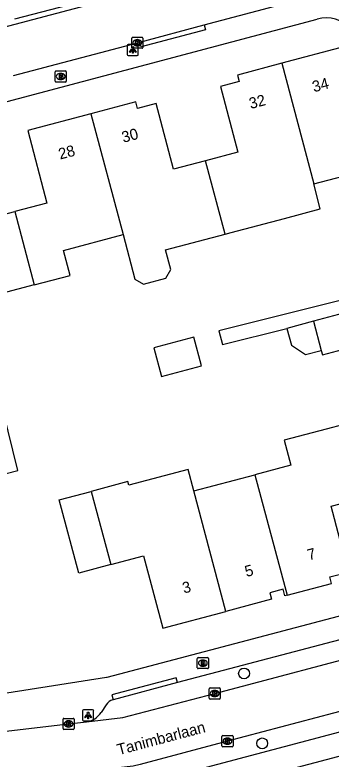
# Model space of a CAD drawing. Extents: x 162880 to 165536, y 384011 to 385179.
# Drawn here: x 163816.8 to 163845.3, y 384374.7 to 384441.9 of the extents above; entities that cross this region are included whole.
import ezdxf

# ---------------------------------------------------------------- set-up
doc = ezdxf.new("R2010")
doc.units = 0
for name, color, linetype in [('IMGEO_Boom', 7, 'Continuous'), ('IMGEO_Brandkraan', 7, 'Continuous'), ('IMGEO_Haag', 7, 'Continuous'), ('IMGEO_Kolk', 7, 'Continuous'), ('IMGEO_Lichtpunt', 7, 'Continuous'), ('IMGEO_Muur', 7, 'Continuous'), ('IMGEO_Openbare_ruimte_label', 7, 'Continuous'), ('IMGEO_Pand', 7, 'Continuous'), ('IMGEO_Pand_nummerreeks', 7, 'Continuous'), ('IMGEO_Rijbaan_lokaal_open', 7, 'Continuous'), ('IMGEO_Voetpad_open', 7, 'Continuous')]:
    doc.layers.add(name, color=color, linetype=linetype)

msp = doc.modelspace()

# ---------------------------------------------------------------- linework, layer by layer
at = {"layer": 'IMGEO_Boom'}
for centre in [(163837.49, 384382.411), (163839.124, 384376.096)]:
    msp.add_circle(centre, 0.489, dxfattribs=at)
at = {"layer": 'IMGEO_Brandkraan'}
for p, q in [((163820.447, 384435.912), (163820.447, 384436.764)), ((163820.522, 384436.838), (163821.374, 384436.838)), ((163820.935, 384436.618), (163820.96, 384436.618)), ((163821.448, 384436.764), (163821.448, 384435.912)), ((163821.374, 384435.838), (163820.522, 384435.838)), ((163820.958, 384436.058), (163820.933, 384436.058)), ((163833.274, 384382.922), (163833.274, 384383.774)), ((163833.349, 384383.848), (163834.201, 384383.848)), ((163833.762, 384383.628), (163833.787, 384383.628)), ((163834.275, 384383.774), (163834.275, 384382.922)), ((163834.201, 384382.848), (163833.349, 384382.848)), ((163833.785, 384383.068), (163833.76, 384383.068))]:
    msp.add_line(p, q, dxfattribs=at)
for points in [[(163820.447, 384435.912), (163820.447, 384436.764)], [(163820.522, 384436.838), (163821.374, 384436.838)], [(163820.795, 384436.538), (163820.795, 384436.138), (163821.008, 384436.138)], [(163821.026, 384436.538), (163820.795, 384436.538)], [(163820.974, 384436.457), (163820.92, 384436.457), (163820.92, 384436.381)], [(163820.92, 384436.381), (163820.973, 384436.381)], [(163821.448, 384436.764), (163821.448, 384435.912)], [(163821.374, 384435.838), (163820.522, 384435.838)], [(163820.982, 384436.305), (163820.92, 384436.305), (163820.92, 384436.224)], [(163820.92, 384436.224), (163820.982, 384436.224)], [(163833.274, 384382.922), (163833.274, 384383.774)], [(163833.349, 384383.848), (163834.201, 384383.848)], [(163833.622, 384383.548), (163833.622, 384383.148), (163833.835, 384383.148)], [(163833.853, 384383.548), (163833.622, 384383.548)], [(163833.801, 384383.467), (163833.747, 384383.467), (163833.747, 384383.391)], [(163833.747, 384383.391), (163833.8, 384383.391)], [(163833.809, 384383.315), (163833.747, 384383.315), (163833.747, 384383.234)], [(163834.275, 384383.774), (163834.275, 384382.922)], [(163834.201, 384382.848), (163833.349, 384382.848)], [(163833.747, 384383.234), (163833.809, 384383.234)]]:
    msp.add_lwpolyline(points, dxfattribs=at)
for centre, radius, start, end in [((163820.524, 384436.762), 0.0765, 91.55205, 178.44795), ((163820.524, 384436.762), 0.0765, 91.55205, 178.44795), ((163820.975, 384436.419), 0.0379, 267.82845, 90.93552), ((163821.03, 384436.393), 0.145, 59.4692, 91.53667), ((163821.055, 384436.44), 0.0922, 285.51372, 58.15012), ((163821.372, 384436.762), 0.0765, 1.55205, 88.44795), ((163821.372, 384436.762), 0.0765, 1.55205, 88.44795), ((163820.524, 384435.914), 0.0765, 181.55205, 268.44795), ((163820.524, 384435.914), 0.0765, 181.55205, 268.44795), ((163820.983, 384436.264), 0.0404, 269.87594, 90.50774), ((163821.014, 384436.389), 0.251, 268.66757, 293.53466), ((163821.06, 384436.248), 0.105, 301.31148, 78.98903), ((163821.372, 384435.914), 0.0765, 271.55205, 358.44795), ((163821.372, 384435.914), 0.0765, 271.55205, 358.44795), ((163833.351, 384383.772), 0.0765, 91.55205, 178.44795), ((163833.351, 384383.772), 0.0765, 91.55205, 178.44795), ((163833.802, 384383.429), 0.0379, 267.82845, 90.93552), ((163833.81, 384383.274), 0.0404, 269.87594, 90.50774), ((163833.857, 384383.403), 0.145, 59.4692, 91.53667), ((163833.882, 384383.45), 0.0922, 285.51372, 58.15012), ((163833.887, 384383.258), 0.105, 301.31148, 78.98903), ((163834.199, 384383.772), 0.0765, 1.55205, 88.44795), ((163834.199, 384383.772), 0.0765, 1.55205, 88.44795), ((163833.351, 384382.924), 0.0765, 181.55205, 268.44795), ((163833.351, 384382.924), 0.0765, 181.55205, 268.44795), ((163833.841, 384383.399), 0.251, 268.66757, 293.53466), ((163834.199, 384382.924), 0.0765, 271.55205, 358.44795), ((163834.199, 384382.924), 0.0765, 271.55205, 358.44795)]:
    msp.add_arc(centre, radius, start, end, dxfattribs=at)
for centre, major_axis, ratio, start_param, end_param in [((163820.934, 384436.338), (-0.387, 0.002), 0.722429, 4.712389, 7.853982), ((163820.959, 384436.338), (-0.39, 0.002), 0.717154, 1.570796, 4.712389), ((163833.761, 384383.348), (-0.387, 0.002), 0.722429, 4.712389, 7.853982), ((163833.786, 384383.348), (-0.39, 0.002), 0.717154, 1.570796, 4.712389)]:
    msp.add_ellipse(centre, major_axis=major_axis, ratio=ratio, start_param=start_param, end_param=end_param, dxfattribs=at)
at = {"layer": 'IMGEO_Haag'}
msp.add_lwpolyline([(163824.084, 384443.45), (163816.786, 384441.509)], dxfattribs=at)
at = {"layer": 'IMGEO_Kolk'}
for p, q in [((163827.363, 384438.958), (163827.363, 384439.81)), ((163827.438, 384439.884), (163828.29, 384439.884)), ((163828.364, 384439.81), (163828.364, 384438.958)), ((163827.874, 384439.104), (163827.849, 384439.104)), ((163827.851, 384439.664), (163827.876, 384439.664)), ((163828.29, 384438.884), (163827.438, 384438.884)), ((163834.343, 384380.178), (163834.343, 384381.03)), ((163834.418, 384381.104), (163835.27, 384381.104)), ((163834.831, 384380.884), (163834.856, 384380.884)), ((163835.344, 384381.03), (163835.344, 384380.178)), ((163835.27, 384380.104), (163834.418, 384380.104)), ((163834.854, 384380.324), (163834.829, 384380.324)), ((163821.155, 384377.427), (163821.155, 384378.279)), ((163821.23, 384378.353), (163822.082, 384378.353)), ((163821.643, 384378.133), (163821.668, 384378.133)), ((163822.156, 384378.279), (163822.156, 384377.427)), ((163822.082, 384377.353), (163821.23, 384377.353)), ((163821.666, 384377.573), (163821.641, 384377.573)), ((163835.492, 384375.869), (163835.492, 384376.721)), ((163835.567, 384376.795), (163836.419, 384376.795)), ((163835.98, 384376.575), (163836.005, 384376.575)), ((163836.493, 384376.721), (163836.493, 384375.869)), ((163836.003, 384376.015), (163835.978, 384376.015)), ((163836.419, 384375.795), (163835.567, 384375.795))]:
    msp.add_line(p, q, dxfattribs=at)
for points in [[(163827.363, 384438.958), (163827.363, 384439.81)], [(163827.438, 384439.884), (163828.29, 384439.884)], [(163828.364, 384439.81), (163828.364, 384438.958)], [(163827.684, 384439.584), (163827.807, 384439.584), (163827.807, 384439.433), (163827.937, 384439.584), (163828.101, 384439.584), (163827.955, 384439.433), (163828.108, 384439.184), (163827.956, 384439.184), (163827.871, 384439.348), (163827.807, 384439.281), (163827.807, 384439.184), (163827.684, 384439.184), (163827.684, 384439.584)], [(163828.29, 384438.884), (163827.438, 384438.884)], [(163834.343, 384380.178), (163834.343, 384381.03)], [(163834.418, 384381.104), (163835.27, 384381.104)], [(163834.664, 384380.804), (163834.787, 384380.804), (163834.787, 384380.653), (163834.917, 384380.804), (163835.081, 384380.804), (163834.935, 384380.653), (163835.088, 384380.404), (163834.936, 384380.404), (163834.851, 384380.568), (163834.787, 384380.501), (163834.787, 384380.404), (163834.664, 384380.404), (163834.664, 384380.804)], [(163835.344, 384381.03), (163835.344, 384380.178)], [(163835.27, 384380.104), (163834.418, 384380.104)], [(163821.155, 384377.427), (163821.155, 384378.279)], [(163821.23, 384378.353), (163822.082, 384378.353)], [(163821.476, 384378.053), (163821.599, 384378.053), (163821.599, 384377.902), (163821.729, 384378.053), (163821.893, 384378.053), (163821.747, 384377.902), (163821.9, 384377.653), (163821.748, 384377.653), (163821.663, 384377.817), (163821.599, 384377.75), (163821.599, 384377.653), (163821.476, 384377.653), (163821.476, 384378.053)], [(163822.156, 384378.279), (163822.156, 384377.427)], [(163822.082, 384377.353), (163821.23, 384377.353)], [(163835.492, 384375.869), (163835.492, 384376.721)], [(163835.567, 384376.795), (163836.419, 384376.795)], [(163836.493, 384376.721), (163836.493, 384375.869)], [(163835.813, 384376.495), (163835.936, 384376.495), (163835.936, 384376.344), (163836.066, 384376.495), (163836.23, 384376.495), (163836.084, 384376.344), (163836.237, 384376.095), (163836.085, 384376.095), (163836, 384376.259), (163835.936, 384376.192), (163835.936, 384376.095), (163835.813, 384376.095), (163835.813, 384376.495)], [(163836.419, 384375.795), (163835.567, 384375.795)]]:
    msp.add_lwpolyline(points, dxfattribs=at)
for centre, start, end in [((163827.44, 384439.808), 91.55205, 178.44795), ((163827.44, 384439.808), 91.55205, 178.44795), ((163828.288, 384439.808), 1.55205, 88.44795), ((163828.288, 384439.808), 1.55205, 88.44795), ((163827.44, 384438.96), 181.55205, 268.44795), ((163827.44, 384438.96), 181.55205, 268.44795), ((163828.288, 384438.96), 271.55205, 358.44795), ((163828.288, 384438.96), 271.55205, 358.44795), ((163834.42, 384381.028), 91.55205, 178.44795), ((163834.42, 384381.028), 91.55205, 178.44795), ((163835.268, 384381.028), 1.55205, 88.44795), ((163835.268, 384381.028), 1.55205, 88.44795), ((163834.42, 384380.18), 181.55205, 268.44795), ((163834.42, 384380.18), 181.55205, 268.44795), ((163835.268, 384380.18), 271.55205, 358.44795), ((163835.268, 384380.18), 271.55205, 358.44795), ((163821.232, 384378.277), 91.55205, 178.44795), ((163821.232, 384378.277), 91.55205, 178.44795), ((163822.08, 384378.277), 1.55205, 88.44795), ((163822.08, 384378.277), 1.55205, 88.44795), ((163821.232, 384377.429), 181.55205, 268.44795), ((163821.232, 384377.429), 181.55205, 268.44795), ((163822.08, 384377.429), 271.55205, 358.44795), ((163822.08, 384377.429), 271.55205, 358.44795), ((163835.569, 384376.719), 91.55205, 178.44795), ((163835.569, 384376.719), 91.55205, 178.44795), ((163836.417, 384376.719), 1.55205, 88.44795), ((163836.417, 384376.719), 1.55205, 88.44795), ((163835.569, 384375.871), 181.55205, 268.44795), ((163835.569, 384375.871), 181.55205, 268.44795), ((163836.417, 384375.871), 271.55205, 358.44795), ((163836.417, 384375.871), 271.55205, 358.44795)]:
    msp.add_arc(centre, 0.0765, start, end, dxfattribs=at)
for centre, major_axis, ratio, start_param, end_param in [((163827.85, 384439.384), (-0.387, 0.002), 0.722429, 4.712389, 7.853982), ((163827.875, 384439.384), (-0.39, 0.002), 0.717154, 1.570796, 4.712389), ((163834.83, 384380.604), (-0.387, 0.002), 0.722429, 4.712389, 7.853982), ((163834.855, 384380.604), (-0.39, 0.002), 0.717154, 1.570796, 4.712389), ((163821.642, 384377.853), (-0.387, 0.002), 0.722429, 4.712389, 7.853982), ((163821.667, 384377.853), (-0.39, 0.002), 0.717154, 1.570796, 4.712389), ((163835.979, 384376.295), (-0.387, 0.002), 0.722429, 4.712389, 7.853982), ((163836.004, 384376.295), (-0.39, 0.002), 0.717154, 1.570796, 4.712389)]:
    msp.add_ellipse(centre, major_axis=major_axis, ratio=ratio, start_param=start_param, end_param=end_param, dxfattribs=at)
at = {"layer": 'IMGEO_Lichtpunt'}
for p, q in [((163826.953, 384439.143), (163826.953, 384438.336)), ((163826.953, 384439.143), (163826.953, 384438.336)), ((163827.855, 384439.238), (163827.047, 384439.238)), ((163827.855, 384439.238), (163827.047, 384439.238)), ((163827.949, 384438.336), (163827.949, 384439.143)), ((163827.949, 384438.336), (163827.949, 384439.143)), ((163827.047, 384438.242), (163827.855, 384438.242)), ((163827.047, 384438.242), (163827.855, 384438.242)), ((163822.925, 384379.033), (163822.925, 384378.226)), ((163822.925, 384379.033), (163822.925, 384378.226)), ((163823.827, 384379.128), (163823.019, 384379.128)), ((163823.827, 384379.128), (163823.019, 384379.128)), ((163823.921, 384378.226), (163823.921, 384379.033)), ((163823.921, 384378.226), (163823.921, 384379.033)), ((163823.019, 384378.132), (163823.827, 384378.132)), ((163823.019, 384378.132), (163823.827, 384378.132))]:
    msp.add_line(p, q, dxfattribs=at)
for points in [[(163827.327, 384438.807), (163827.366, 384438.779), (163827.178, 384438.517), (163827.14, 384438.544), (163827.327, 384438.807)], [(163827.429, 384438.759), (163827.476, 384438.759), (163827.476, 384438.437), (163827.429, 384438.437), (163827.429, 384438.759)], [(163827.539, 384438.779), (163827.577, 384438.806), (163827.764, 384438.544), (163827.725, 384438.516), (163827.539, 384438.779)], [(163823.299, 384378.697), (163823.338, 384378.669), (163823.15, 384378.407), (163823.112, 384378.434), (163823.299, 384378.697)], [(163823.401, 384378.649), (163823.448, 384378.649), (163823.448, 384378.327), (163823.401, 384378.327), (163823.401, 384378.649)], [(163823.511, 384378.669), (163823.549, 384378.696), (163823.736, 384378.434), (163823.697, 384378.406), (163823.511, 384378.669)]]:
    msp.add_lwpolyline(points, dxfattribs=at)
for centre in [(163827.452, 384438.941), (163823.424, 384378.831)]:
    msp.add_circle(centre, 0.0994, dxfattribs=at)
for centre, start, end in [((163827.047, 384439.143), 90, 180), ((163827.047, 384439.143), 90, 180), ((163827.855, 384439.143), 0, 90), ((163827.855, 384439.143), 0, 90), ((163827.047, 384438.336), 180, 270), ((163827.047, 384438.336), 180, 270), ((163827.855, 384438.336), 270, 0), ((163827.855, 384438.336), 270, 360), ((163823.019, 384379.033), 90, 180), ((163823.019, 384379.033), 90, 180), ((163823.827, 384379.033), 0, 90), ((163823.827, 384379.033), 0, 90), ((163823.019, 384378.226), 180, 270), ((163823.019, 384378.226), 180, 270), ((163823.827, 384378.226), 270, 0), ((163823.827, 384378.226), 270, 360)]:
    msp.add_arc(centre, 0.0946, start, end, dxfattribs=at)
at = {"layer": 'IMGEO_Muur'}
msp.add_lwpolyline([(163816.096, 384380.674), (163825.065, 384382.078)], dxfattribs=at)
at = {"layer": 'IMGEO_Pand'}
for points in [[(163843.778, 384426.625), (163849.087, 384428.034), (163849.377, 384426.941), (163853.021, 384427.908), (163850.932, 384432.352), (163848.381, 384432.327), (163846.597, 384439.044), (163840.884, 384437.528)], [(163840.884, 384437.528), (163836.884, 384436.466), (163837.038, 384435.887), (163835.351, 384435.436), (163836.94, 384429.495), (163834.011, 384428.723)], [(163840.884, 384437.528), (163843.778, 384426.625)], [(163834.011, 384428.723), (163831.125, 384427.963), (163829.555, 384433.899), (163827.872, 384433.454), (163827.718, 384434.033), (163823.678, 384432.96)], [(163823.678, 384432.96), (163817.994, 384431.451), (163819.71, 384424.904), (163816.817, 384424.136)], [(163823.678, 384432.96), (163826.572, 384422.049)], [(163835.776, 384422.09), (163834.011, 384428.723)], [(163835.776, 384422.09), (163836.318, 384422.234), (163841.15, 384423.517), (163844.365, 384424.371), (163843.778, 384426.625)], [(163818.545, 384417.508), (163815.6, 384416.726), (163813.843, 384423.347), (163816.817, 384424.136)], [(163816.817, 384424.136), (163818.545, 384417.508)], [(163818.545, 384417.508), (163821.794, 384418.37), (163821.196, 384420.622), (163826.572, 384422.049)], [(163826.572, 384422.049), (163827.635, 384418.039), (163828.431, 384417.577), (163830.419, 384418.105), (163830.88, 384418.9), (163830.412, 384420.667), (163835.776, 384422.09)], [(163847.823, 384415.315), (163843.743, 384414.223)], [(163844.446, 384411.597), (163844.555, 384411.188), (163848.635, 384412.281), (163847.823, 384415.315)], [(163843.743, 384414.223), (163841.358, 384413.585)], [(163843.743, 384414.223), (163844.446, 384411.597)], [(163841.358, 384413.585), (163841.761, 384412.08), (163843.029, 384411.218), (163844.446, 384411.597)], [(163829.359, 384411.839), (163830.05, 384409.238), (163833.647, 384410.192), (163832.957, 384412.793), (163829.359, 384411.839)], [(163815.575, 384396.648), (163815.298, 384397.976), (163814.837, 384400.18), (163817.093, 384400.732), (163815.77, 384406.136), (163813.167, 384405.499)], [(163846.484, 384404.902), (163844.892, 384404.481), (163841.103, 384403.478), (163841.699, 384401.225), (163838.461, 384400.366)], [(163832.96, 384398.908), (163832.445, 384400.849), (163827.089, 384399.429), (163827.007, 384399.738), (163823.706, 384398.863)], [(163832.96, 384398.908), (163838.461, 384400.366)], [(163838.461, 384400.366), (163841.393, 384389.491)], [(163825.485, 384392.258), (163822.572, 384391.486), (163820.82, 384398.098), (163823.706, 384398.863)], [(163823.706, 384398.863), (163825.485, 384392.258)], [(163835.849, 384388.021), (163832.96, 384398.908)], [(163841.393, 384389.491), (163845.392, 384390.551), (163845.236, 384391.141), (163846.918, 384391.573), (163845.347, 384397.519), (163848.238, 384398.285)], [(163825.485, 384392.258), (163828.429, 384393.038), (163830.158, 384386.513), (163835.849, 384388.021)], [(163841.393, 384389.491), (163841.178, 384389.434), (163841.025, 384390.014), (163839.807, 384389.692), (163839.96, 384389.111), (163835.849, 384388.021)]]:
    msp.add_lwpolyline(points, dxfattribs=at)
at = {"layer": 'IMGEO_Rijbaan_lokaal_open'}
for points in [[(163782.356, 384431.947), (163812.597, 384439.959), (163829.593, 384444.462), (163830.022, 384444.577), (163841.66, 384447.709), (163843.285, 384448.142)], [(163833.898, 384440.995), (163844.487, 384443.826)], [(163828.078, 384439.436), (163833.898, 384440.995)], [(163816.688, 384436.424), (163827.864, 384439.385), (163828.078, 384439.436)], [(163823.263, 384378.046), (163826.557, 384378.434), (163834.844, 384380.604), (163865.713, 384388.799), (163868.168, 384389.455)], [(163869.972, 384385.282), (163867.877, 384384.716), (163851.935, 384380.508), (163835.992, 384376.295), (163828.118, 384374.191), (163827.488, 384374.039), (163824.303, 384373.665)], [(163802.736, 384375.641), (163803.948, 384375.773), (163821.656, 384377.851), (163823.263, 384378.046)]]:
    msp.add_lwpolyline(points, dxfattribs=at)
at = {"layer": 'IMGEO_Voetpad_open'}
for points in [[(163805.887, 384431.366), (163811.331, 384432.813), (163844.085, 384441.522)], [(163833.898, 384440.995), (163834.015, 384440.558), (163828.203, 384439.02), (163828.078, 384439.436)], [(163851.275, 384417.658), (163850.017, 384417.071), (163835.223, 384413.352), (163835.531, 384412.127), (163841.358, 384413.585)], [(163802.92, 384378.611), (163816.096, 384380.674), (163825.065, 384382.078), (163825.148, 384382.091), (163865.727, 384392.809)], [(163848.431, 384386.065), (163831.487, 384381.581)], [(163831.487, 384381.581), (163831.374, 384382.003), (163825.558, 384380.472), (163825.666, 384380.027)], [(163871.845, 384381.733), (163828.311, 384370.22), (163828.207, 384370.211), (163817.519, 384369.317), (163804.137, 384368.197)], [(163831.487, 384381.581), (163825.666, 384380.027)], [(163825.046, 384379.585), (163824.603, 384378.892)], [(163850.07, 384378.169), (163833.614, 384373.811)]]:
    msp.add_lwpolyline(points, dxfattribs=at)
for centre, radius, start, end in [((163844.897, 384438.899), 2.746, 37.23049, 107.18866), ((163825.904, 384379.037), 1.019, 103.53904, 147.43135), ((163822.981, 384379.977), 1.951, 278.30776, 326.22422)]:
    msp.add_arc(centre, radius, start, end, dxfattribs=at)

# ---------------------------------------------------------------- texts
at = {"layer": 'IMGEO_Openbare_ruimte_label'}
msp.add_text('Tanimbarlaan', height=1, rotation=14.89819, dxfattribs=at).set_placement((163826.182, 384375.026))
at = {"layer": 'IMGEO_Pand_nummerreeks'}
for s, rotation, p in [('34', 14.86253, (163843.79, 384434.906)), ('32', 14.86458, (163838.086, 384433.391)), ('30', 14.87052, (163826.596, 384430.342)), ('28', 14.87052, (163820.892, 384428.827)), ('7', 14.84573, (163843.34, 384392.615)), ('5', 14.84573, (163837.702, 384391.121)), ('3', 14.84573, (163832.065, 384389.626))]:
    msp.add_text(s, height=1, rotation=rotation, dxfattribs=at).set_placement(p)

doc.saveas('drawing.dxf')
